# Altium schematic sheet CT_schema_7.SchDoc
size 278 x 170 mm
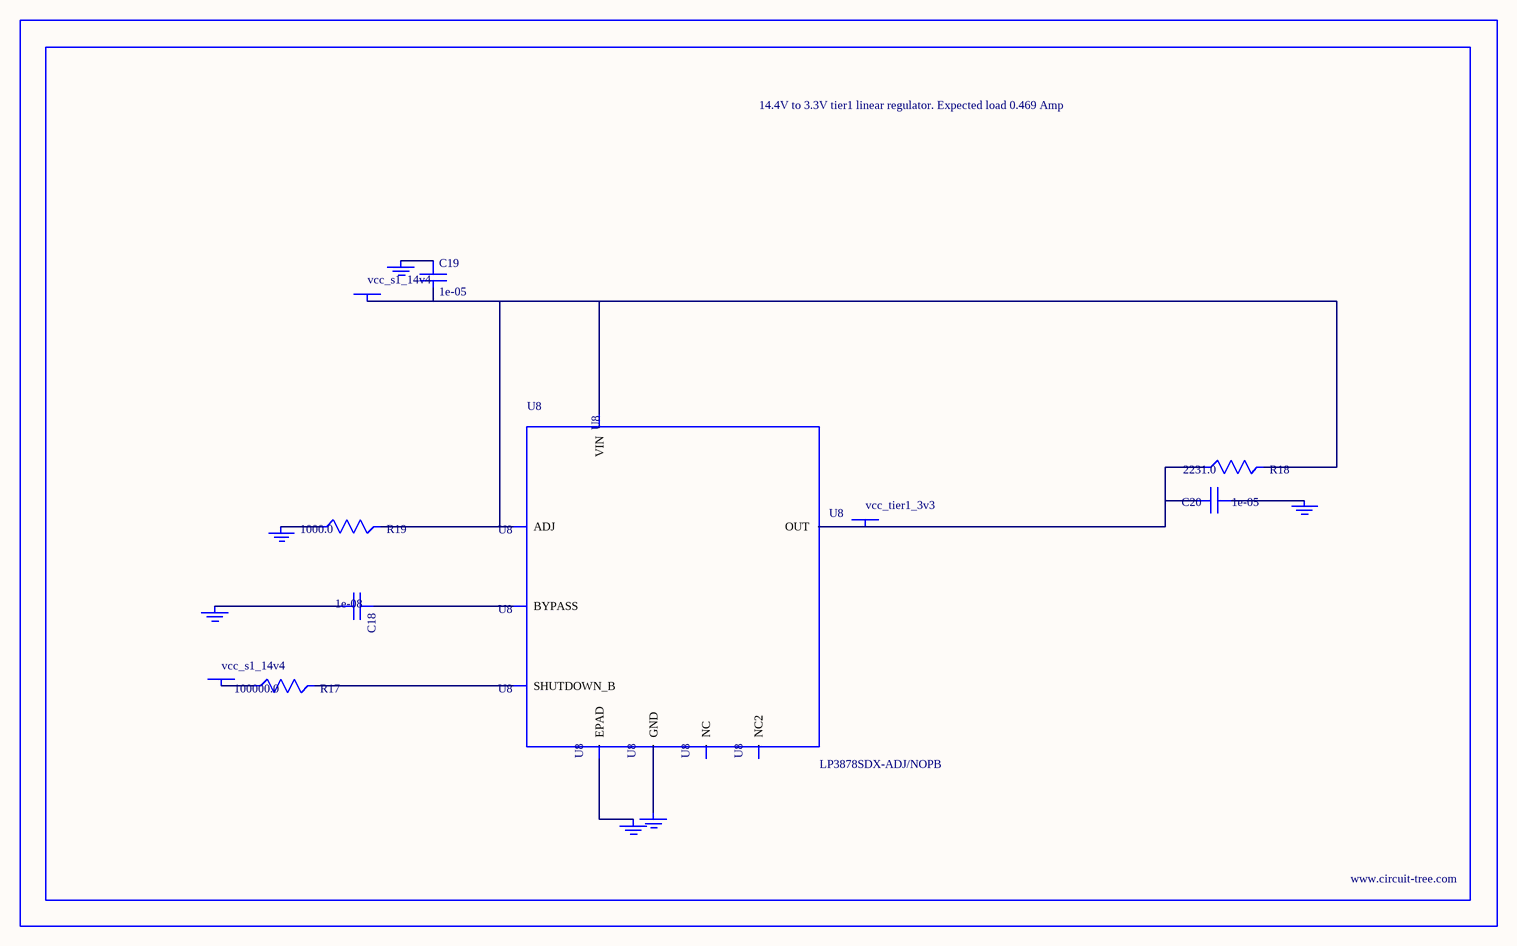
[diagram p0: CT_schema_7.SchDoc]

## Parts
BORDER6  (no value)
C18  1e-08  [C0402]
C19  1e-05  [C1210]
C20  1e-05  [C1210]
GND_INSTANCE_6_0  (no value)
GND_INSTANCE_6_1  (no value)
GND_INSTANCE_6_2  (no value)
GND_INSTANCE_6_3  (no value)
GND_INSTANCE_6_4  (no value)
GND_INSTANCE_6_5  (no value)
POWER_INSTANCE_6_0  vcc_s1_14v4
POWER_INSTANCE_6_1  vcc_s1_14v4
POWER_INSTANCE_6_2  vcc_tier1_3v3
R17  100000.0  [R0603]
R18  2231.0  [R0603]
R19  1000.0  [R0603]
U8  LP3878SDX-ADJ/NOPB  [WSON-8]

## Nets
NetC18_1: C18.1 U8.1(BYPASS)
NetC18_2: C18.2 GND_INSTANCE_6_0.0(GND)
NetC19_1: C19.1 GND_INSTANCE_6_1.0(GND)
NetC19_2: C19.2 POWER_INSTANCE_6_0.0(PWR) R18.2 R19.2 U8.4(VIN) U8.6(ADJ)
NetC20_1: C20.1 GND_INSTANCE_6_2.0(GND)
NetC20_2: C20.2 POWER_INSTANCE_6_2.0(PWR) R18.1 U8.5(OUT)
NetGND_INSTANCE_6_3_0: GND_INSTANCE_6_3.0(GND) R19.1
NetGND_INSTANCE_6_4_0: GND_INSTANCE_6_4.0(GND) U8.PAD(EPAD)
NetGND_INSTANCE_6_5_0: GND_INSTANCE_6_5.0(GND) U8.3(GND)
NetPOWER_INSTANCE_6_1_0: POWER_INSTANCE_6_1.0(PWR) R17.1
NetR17_2: R17.2 U8.8(SHUTDOWN_B)

Not connected (* = marked no-connect by the designer): U8 2(NC) 7(NC2)

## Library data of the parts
BORDER6 = BORDER_PAGE6
C18 = C0402C103K3RAC
C19 = C1210C106K5PACTU
C20 = GRM32DR61E106MA12L
GND_INSTANCE_6_0-GND_INSTANCE_6_5 = GND
POWER_INSTANCE_6_0-POWER_INSTANCE_6_2 = PWR
R17 = RC0603JR-07100KL
R18 = R18
R19 = RC0603JR-071KL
